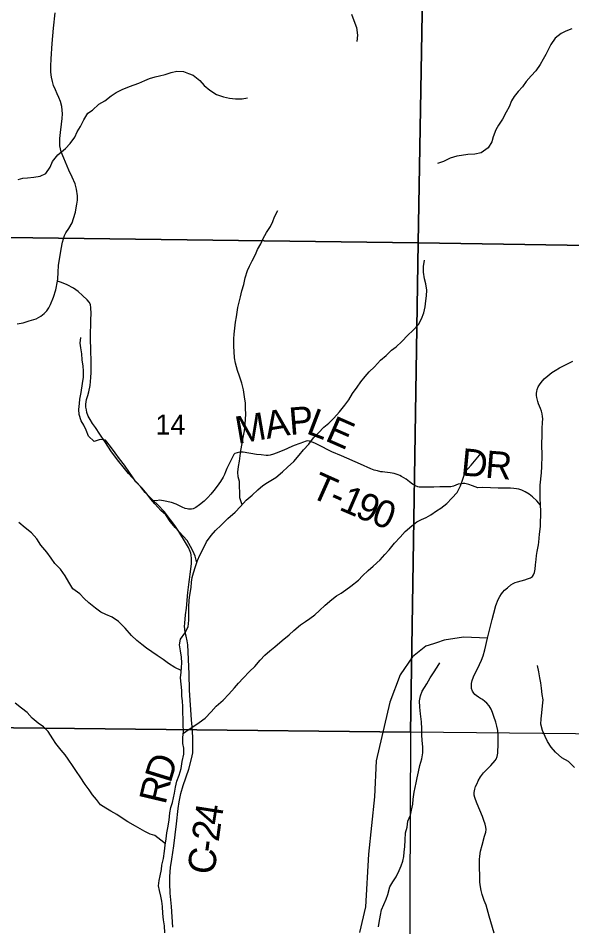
# Model space of a CAD drawing. Extents: x 0 to 34, y 0 to 22.
# Drawn here: x 24.164 to 25.315, y 15.161 to 17.051 of the extents above; entities that cross this region are included whole.
import ezdxf

# ---------------------------------------------------------------- set-up
doc = ezdxf.new("R2010")
doc.units = 0
for name, color, linetype in [('GM_X_Corporation', 7, 'Continuous'), ('GM_X_County_Road', 7, 'Continuous'), ('GM_X_County_Road_Text', 7, 'Continuous'), ('GM_X_Minor_River', 7, 'Continuous'), ('GM_X_Section_Text', 7, 'Continuous'), ('GM_X_State_Route', 7, 'Continuous'), ('GM_X_Township_Road', 7, 'Continuous'), ('GM_X_Township_Road_Text', 7, 'Continuous')]:
    doc.layers.add(name, color=color, linetype=linetype)

msp = doc.modelspace()

# ---------------------------------------------------------------- linework, layer by layer
at = {"layer": 'GM_X_Corporation'}
for points in [[(25.0136, 17.617), (24.9957, 16.5834), (23.9803, 16.5962), (23.994, 17.626)], [(26.0272, 17.5944), (26.0142, 16.5672), (24.9957, 16.5834), (25.0136, 17.617)], [(23.9803, 16.5962), (24.9957, 16.5834), (24.9795, 15.5656), (23.9634, 15.5762)], [(24.9957, 16.5834), (26.0142, 16.5672), (26.0085, 15.5549), (24.9795, 15.5656)], [(23.9634, 15.5762), (24.9795, 15.5656), (24.9754, 14.552), (23.9615, 14.5614), (23.9614, 14.5662)]]:
    msp.add_lwpolyline(points, close=True, dxfattribs=at)
at = {"layer": 'GM_X_County_Road'}
msp.add_lwpolyline([(24.4858, 15.1598), (24.4828, 15.2031), (24.4802, 15.2302), (24.4792, 15.2509), (24.4792, 15.2655), (24.481, 15.2837), (24.4834, 15.3015), (24.4879, 15.3293), (24.4933, 15.3746), (24.4964, 15.4066), (24.4984, 15.4204), (24.5022, 15.4376), (24.5073, 15.4548), (24.5188, 15.4884), (24.5245, 15.5097), (24.5269, 15.5223), (24.5274, 15.538), (24.5271, 15.5551), (24.5259, 15.5763), (24.5241, 15.5911), (24.5203, 15.6531), (24.5195, 15.6867), (24.5166, 15.7472), (24.5154, 15.7557), (24.5132, 15.7649), (24.5113, 15.7727), (24.5103, 15.7802), (24.5101, 15.7853), (24.5103, 15.7921), (24.5121, 15.8093), (24.5138, 15.8237), (24.5169, 15.8557), (24.5196, 15.878), (24.5202, 15.8827), (24.5218, 15.8939), (24.524, 15.9159), (24.5245, 15.9259), (24.5238, 15.934), (24.5228, 15.938), (24.5217, 15.9412), (24.5178, 15.9498), (24.512, 15.9601), (24.4979, 15.9829), (24.4898, 15.9952), (24.4807, 16.0072), (24.4674, 16.0244), (24.4541, 16.0381), (24.4445, 16.0471), (24.437, 16.0547), (24.4283, 16.0643), (24.418, 16.0766), (24.3936, 16.1034), (24.3822, 16.1171), (24.3734, 16.1284), (24.3645, 16.1402), (24.3568, 16.1507), (24.3454, 16.168), (24.3339, 16.1855), (24.3246, 16.1991), (24.3184, 16.2078), (24.3138, 16.2155), (24.3098, 16.2231), (24.307, 16.2302), (24.3059, 16.2359), (24.305, 16.2413), (24.3047, 16.2479), (24.3063, 16.2572), (24.3085, 16.266), (24.3108, 16.2735), (24.3134, 16.2866), (24.3153, 16.3033), (24.3157, 16.3139), (24.3157, 16.3235), (24.3156, 16.3382), (24.3151, 16.3585), (24.3144, 16.3858), (24.3154, 16.4234), (24.3159, 16.4366), (24.3154, 16.4482), (24.3141, 16.4548), (24.3116, 16.4598), (24.3075, 16.4648), (24.298, 16.474), (24.2888, 16.4818), (24.2787, 16.489), (24.2657, 16.4958), (24.2541, 16.5009), (24.2457, 16.5036)], dxfattribs=at)
at = {"layer": 'GM_X_Minor_River'}
for points in [[(24.8569, 17.0592), (24.8619, 17.0456), (24.8672, 17.0315), (24.8692, 17.0152), (24.8677, 17.0019)], [(25.315, 17.0288), (25.3025, 17.0238), (25.2926, 17.0188), (25.2801, 17.0089), (25.2711, 16.9956), (25.2658, 16.9846), (25.2609, 16.9751), (25.2552, 16.9652), (25.2491, 16.9545), (25.2401, 16.9409), (25.2302, 16.9306), (25.22, 16.9188), (25.212, 16.9081), (25.203, 16.8982), (25.195, 16.8879), (25.1893, 16.8784), (25.1844, 16.8663), (25.1784, 16.8549), (25.1705, 16.8404), (25.1621, 16.8282), (25.1572, 16.8187), (25.1516, 16.8039), (25.1489, 16.7937), (25.141, 16.7807), (25.1262, 16.7704), (25.1129, 16.7681), (25.0989, 16.7673), (25.0856, 16.765), (25.0758, 16.7634), (25.0617, 16.7592), (25.0481, 16.7527), (25.0356, 16.7481)], [(24.3799, 16.9024), (24.3955, 16.9086), (24.4049, 16.912), (24.4148, 16.9154), (24.4273, 16.9208), (24.4372, 16.925), (24.4485, 16.9288), (24.458, 16.9308), (24.4694, 16.9338), (24.4819, 16.9377), (24.4937, 16.9404), (24.5077, 16.9397), (24.518, 16.9355), (24.5278, 16.9321), (24.5415, 16.9212), (24.5503, 16.9106), (24.5624, 16.9011), (24.5765, 16.892), (24.5909, 16.8872), (24.6031, 16.8845), (24.616, 16.8831), (24.6296, 16.8831), (24.641, 16.885)], [(24.1637, 16.7154), (24.1735, 16.7177), (24.1834, 16.7185), (24.1967, 16.72), (24.2096, 16.722), (24.2217, 16.7273), (24.2308, 16.7406), (24.2353, 16.7524), (24.2463, 16.7661), (24.2622, 16.7794), (24.2724, 16.7897), (24.2815, 16.803), (24.2868, 16.8141), (24.2936, 16.8251), (24.3007, 16.8392), (24.3087, 16.8529), (24.3185, 16.8593), (24.3318, 16.8719), (24.3443, 16.8788), (24.3575, 16.8891), (24.3674, 16.8959), (24.3799, 16.9024)], [(24.6294, 16.0386), (24.625, 16.0526), (24.6246, 16.0651), (24.6242, 16.0749), (24.6238, 16.0867), (24.6215, 16.0966), (24.6207, 16.1061), (24.6222, 16.1182), (24.6241, 16.1289), (24.6256, 16.1406), (24.6271, 16.1513), (24.6297, 16.1661), (24.6316, 16.1782), (24.6346, 16.1923), (24.6361, 16.2063), (24.6368, 16.2166), (24.6372, 16.2272), (24.6367, 16.2386), (24.6363, 16.2496), (24.6348, 16.2633), (24.6321, 16.2777), (24.6287, 16.2917), (24.6241, 16.3057), (24.6199, 16.3175), (24.6161, 16.3327), (24.6137, 16.3444), (24.613, 16.3573), (24.6126, 16.3676), (24.6125, 16.3835), (24.6129, 16.393), (24.6144, 16.4055), (24.6159, 16.4184), (24.6177, 16.4291), (24.6207, 16.4488), (24.6237, 16.4598), (24.6264, 16.4712), (24.629, 16.4838), (24.6328, 16.4967), (24.6358, 16.5104), (24.6407, 16.5256), (24.6448, 16.5351), (24.6501, 16.5461), (24.6573, 16.559), (24.6618, 16.5693), (24.6682, 16.5815), (24.6732, 16.5925), (24.68, 16.6047), (24.6883, 16.6176), (24.6932, 16.6275), (24.697, 16.6377), (24.7038, 16.6507)], [(24.8204, 16.2187), (24.8318, 16.232), (24.8428, 16.2457), (24.8515, 16.2564), (24.859, 16.2697), (24.8689, 16.283), (24.8764, 16.2944), (24.8855, 16.3054), (24.8935, 16.3149), (24.9048, 16.3256), (24.9173, 16.3393), (24.9291, 16.3492), (24.94, 16.3599), (24.9499, 16.3668), (24.9616, 16.3778), (24.9738, 16.3911), (24.9844, 16.401), (24.9961, 16.4136), (25.0025, 16.4254), (25.007, 16.4375), (25.0097, 16.4501), (25.0112, 16.463), (25.0127, 16.4729), (25.0138, 16.4846), (25.0111, 16.4983), (25.0084, 16.5085), (25.0065, 16.5222), (25.0068, 16.534), (25.0087, 16.5472)], [(24.5351, 15.9175), (24.5316, 15.9316), (24.5277, 15.9414), (24.5224, 15.952), (24.5152, 15.9641), (24.4901, 15.9914), (24.4802, 16.0035), (24.4707, 16.0175), (24.4604, 16.0266), (24.4478, 16.0406), (24.4398, 16.0504), (24.4319, 16.0607), (24.4216, 16.0732), (24.4087, 16.0864), (24.4018, 16.0963), (24.3953, 16.1057), (24.385, 16.1209), (24.3748, 16.1337), (24.3656, 16.1466), (24.3557, 16.1599), (24.3455, 16.1727), (24.3345, 16.1742), (24.3223, 16.1704), (24.3105, 16.181), (24.3052, 16.1935), (24.3006, 16.2037), (24.2949, 16.2132), (24.2911, 16.2261), (24.2899, 16.2363), (24.2914, 16.2489), (24.2925, 16.2584), (24.2948, 16.2717), (24.2978, 16.2906), (24.2996, 16.3039), (24.3, 16.3172), (24.2992, 16.3271), (24.2973, 16.34), (24.2961, 16.3521), (24.2946, 16.365), (24.293, 16.3745), (24.2945, 16.3863)], [(24.4692, 15.1483), (24.468, 15.1623), (24.4664, 15.1748), (24.4649, 15.1885), (24.4637, 15.2025), (24.4626, 15.2139), (24.4603, 15.2242), (24.4576, 15.2363), (24.4557, 15.2458), (24.4568, 15.2568), (24.4594, 15.2663), (24.462, 15.2796), (24.4628, 15.2891), (24.4658, 15.3027), (24.468, 15.3179), (24.4699, 15.3301), (24.4718, 15.3434), (24.4732, 15.3563), (24.4751, 15.3662), (24.4777, 15.3821), (24.4792, 15.3973), (24.4815, 15.4087), (24.4845, 15.4193), (24.489, 15.4383), (24.4913, 15.4509), (24.4939, 15.4634), (24.4988, 15.4763), (24.5025, 15.4896), (24.5052, 15.5044), (24.5086, 15.5196), (24.5085, 15.5322), (24.5066, 15.5416), (24.5066, 15.5542), (24.5077, 15.5671), (24.5069, 15.5804), (24.5069, 15.5925), (24.5065, 15.6062), (24.5061, 15.6179), (24.5053, 15.6308), (24.5045, 15.6403), (24.5045, 15.6521), (24.5014, 15.6787), (24.5029, 15.6904), (24.5036, 15.6999), (24.5043, 15.7094), (24.5036, 15.7216), (24.5013, 15.7348), (24.4997, 15.747), (24.5016, 15.7587), (24.5103, 15.7717), (24.5171, 15.7846), (24.5189, 15.7983), (24.5189, 15.8256), (24.5196, 15.8397), (24.5211, 15.8507), (24.5234, 15.8662), (24.5245, 15.8776), (24.526, 15.8871), (24.5282, 15.897), (24.5327, 15.9103), (24.5369, 15.9228), (24.5414, 15.9335), (24.5486, 15.9468), (24.5558, 15.9616), (24.5652, 15.9746), (24.5739, 15.9848), (24.5861, 15.9959), (24.5997, 16.0096), (24.6152, 16.0233), (24.6262, 16.0351), (24.6379, 16.048), (24.6504, 16.0583), (24.6625, 16.0694), (24.6728, 16.0785), (24.6826, 16.085), (24.6993, 16.0949), (24.7137, 16.1071), (24.7239, 16.117), (24.7372, 16.1288), (24.7481, 16.1414), (24.7568, 16.1524), (24.7682, 16.1642), (24.778, 16.1776), (24.7883, 16.1878), (24.7992, 16.1996), (24.8095, 16.2084), (24.8204, 16.2187)], [(24.5074, 15.5633), (24.5194, 15.572), (24.5289, 15.5778), (24.5403, 15.5854), (24.5528, 15.5946), (24.5649, 15.6075), (24.5759, 15.6197), (24.5903, 15.6319), (24.6016, 15.6444), (24.6137, 15.6574), (24.6221, 15.6673), (24.6319, 15.6779), (24.6452, 15.6913), (24.6558, 15.7023), (24.6671, 15.7152), (24.677, 15.7255), (24.6872, 15.7347), (24.6974, 15.7427), (24.7129, 15.756), (24.727, 15.7682), (24.7368, 15.7766), (24.7512, 15.7884), (24.761, 15.7953), (24.7705, 15.8021), (24.7804, 15.8097), (24.7902, 15.8185), (24.8023, 15.8299), (24.816, 15.8417), (24.8254, 15.849), (24.8357, 15.8547), (24.8451, 15.8616), (24.8554, 15.8688), (24.8713, 15.8814), (24.88, 15.8909), (24.8913, 15.9016), (24.9016, 15.9107), (24.9163, 15.9241), (24.9262, 15.9347), (24.9349, 15.945), (24.9466, 15.9587), (24.958, 15.9709), (24.9682, 15.9827), (24.9822, 15.9949), (24.9924, 16.0029), (25.0023, 16.0075), (25.0118, 16.012), (25.0216, 16.0174), (25.0334, 16.0258), (25.0428, 16.0315), (25.0553, 16.041), (25.0656, 16.0525), (25.0762, 16.0643), (25.0833, 16.0779), (25.0886, 16.0916), (25.0931, 16.1072), (25.1053, 16.1205), (25.1162, 16.1331), (25.1264, 16.1456)], [(24.5031, 15.6935), (24.4896, 15.6999), (24.4766, 15.7086), (24.4652, 15.7165), (24.4527, 15.7248), (24.4421, 15.7327), (24.4307, 15.7399), (24.4208, 15.7479), (24.4105, 15.7558), (24.3999, 15.7668), (24.3866, 15.7819), (24.3725, 15.7955), (24.3592, 15.805), (24.3459, 15.8099), (24.336, 15.8148), (24.3246, 15.8231), (24.3109, 15.8348), (24.301, 15.8435), (24.2919, 15.8533), (24.2775, 15.8635), (24.2691, 15.8772), (24.2615, 15.8908), (24.2523, 15.9048), (24.2405, 15.9162), (24.2326, 15.9272), (24.2234, 15.94), (24.2109, 15.9544), (24.2025, 15.9673), (24.1915, 15.9802), (24.1789, 15.9908), (24.1652, 16.0017)], [(24.9131, 15.1603), (24.9146, 15.1698), (24.9172, 15.1846), (24.9195, 15.1956), (24.924, 15.207), (24.9289, 15.2181), (24.9327, 15.2276), (24.9364, 15.2435), (24.9425, 15.2542), (24.95, 15.2644), (24.9561, 15.2774), (24.9599, 15.2876), (24.9636, 15.2971), (24.9655, 15.3066), (24.9666, 15.3161), (24.9674, 15.3279), (24.9685, 15.3408), (24.9692, 15.356), (24.9726, 15.3678), (24.9741, 15.3803), (24.9794, 15.3925), (24.9816, 15.4035), (24.9842, 15.416), (24.9854, 15.4263), (24.9872, 15.4403), (24.9891, 15.4502), (24.9914, 15.4601), (24.9932, 15.4703), (24.9959, 15.4832), (24.9992, 15.4958), (25.003, 15.5098), (25.0049, 15.5227), (25.0052, 15.5349), (25.0041, 15.5478), (25.0029, 15.5599), (25.0032, 15.5721), (25.0025, 15.5869), (25.0005, 15.6036), (24.999, 15.6172), (24.9982, 15.6309), (25.0001, 15.6412), (25.0035, 15.6507), (25.0133, 15.6659), (25.0205, 15.6784), (25.0273, 15.6887), (25.0352, 15.7005), (25.0405, 15.71)], [(25.3206, 15.4919), (25.3081, 15.5047), (25.2944, 15.5123), (25.2811, 15.524), (25.272, 15.5342), (25.264, 15.5463), (25.2594, 15.5566), (25.2537, 15.5691), (25.2506, 15.5824), (25.2514, 15.593), (25.2525, 15.6059), (25.254, 15.6199), (25.2551, 15.6329), (25.2532, 15.6435), (25.2516, 15.6568), (25.2501, 15.6681), (25.2485, 15.6784), (25.2462, 15.6909), (25.2435, 15.7042)], [(24.4703, 15.3329), (24.4604, 15.3411), (24.4482, 15.3505), (24.4383, 15.3535), (24.4273, 15.3588), (24.4178, 15.3645), (24.4076, 15.3701), (24.392, 15.3792), (24.3802, 15.3864), (24.3688, 15.3939), (24.3563, 15.4011), (24.346, 15.4071), (24.3354, 15.4143), (24.3266, 15.4253), (24.3186, 15.4351), (24.3118, 15.4454), (24.303, 15.4567), (24.2927, 15.4726), (24.2855, 15.4836), (24.2783, 15.4938), (24.268, 15.509), (24.2619, 15.5185), (24.2532, 15.5283), (24.2425, 15.5419), (24.2364, 15.5518), (24.2265, 15.5669), (24.217, 15.5764), (24.2056, 15.5839), (24.1934, 15.5949), (24.1824, 15.6066), (24.171, 15.6157), (24.1581, 15.6255)]]:
    msp.add_lwpolyline(points, dxfattribs=at)
at = {"layer": 'GM_X_State_Route'}
msp.add_lwpolyline([(24.1617, 16.4145), (24.1746, 16.4171), (24.1869, 16.4211), (24.2012, 16.4255), (24.2109, 16.4305), (24.2182, 16.4361), (24.2234, 16.4418), (24.2275, 16.4479), (24.2314, 16.4552), (24.2377, 16.4702), (24.2423, 16.4856), (24.2457, 16.5036), (24.2464, 16.5084), (24.2471, 16.5218), (24.248, 16.5372), (24.2512, 16.557), (24.2534, 16.5704), (24.2562, 16.5849), (24.2582, 16.5919), (24.2603, 16.5983), (24.2634, 16.6042), (24.2696, 16.6132), (24.2761, 16.6248), (24.2793, 16.6342), (24.283, 16.6471), (24.2848, 16.6559), (24.2863, 16.6635), (24.2871, 16.6721), (24.2873, 16.6814), (24.285, 16.695), (24.2823, 16.7061), (24.2761, 16.72), (24.2696, 16.7343), (24.2586, 16.7597), (24.2536, 16.7725), (24.2509, 16.7849), (24.2503, 16.7918), (24.2503, 16.8002), (24.2518, 16.8126), (24.2539, 16.8302), (24.2555, 16.8419), (24.2559, 16.852), (24.2557, 16.8592), (24.2546, 16.8671), (24.2521, 16.8774), (24.2487, 16.8858), (24.2453, 16.8933), (24.2416, 16.9017), (24.2377, 16.9105), (24.2352, 16.9187), (24.233, 16.9276), (24.2318, 16.9383), (24.2316, 16.951), (24.2326, 16.9664), (24.235, 16.9982), (24.2378, 17.0302), (24.2412, 17.0618)], dxfattribs=at)
at = {"layer": 'GM_X_Township_Road'}
for points in [[(25.1532, 15.147), (25.1433, 15.1827), (25.1366, 15.2053), (25.1328, 15.215), (25.1286, 15.2275), (25.1262, 15.2362), (25.1248, 15.244), (25.1239, 15.2533), (25.1236, 15.263), (25.1229, 15.2874), (25.1229, 15.3003), (25.1239, 15.3078), (25.1253, 15.3181), (25.1282, 15.3303), (25.1332, 15.349), (25.1359, 15.3577), (25.1367, 15.3628), (25.1363, 15.3677), (25.1345, 15.3744), (25.1322, 15.3818), (25.1293, 15.39), (25.118, 15.4162), (25.1145, 15.4256), (25.1131, 15.4297), (25.1119, 15.4344), (25.1121, 15.4402), (25.1132, 15.4466), (25.1148, 15.4521), (25.1179, 15.4589), (25.1203, 15.4644), (25.1251, 15.4722), (25.1315, 15.4808), (25.1379, 15.4879), (25.1465, 15.4959), (25.1554, 15.5062), (25.1577, 15.5093), (25.1597, 15.5146), (25.1608, 15.522), (25.1614, 15.5416), (25.1615, 15.56), (25.1611, 15.569), (25.1593, 15.5776), (25.1567, 15.5864), (25.1528, 15.5977), (25.1501, 15.6061), (25.1472, 15.6135), (25.1428, 15.6201), (25.1384, 15.6255), (25.1343, 15.6295), (25.1295, 15.6331), (25.1253, 15.6355), (25.1212, 15.6384), (25.116, 15.6417), (25.1131, 15.6439), (25.1113, 15.6465), (25.1081, 15.6506), (25.1066, 15.6561), (25.106, 15.6609), (25.1062, 15.6665), (25.1077, 15.673), (25.1105, 15.6808), (25.123, 15.7062), (25.1268, 15.7149), (25.1304, 15.7243), (25.1342, 15.7368), (25.1398, 15.7612), (25.149, 15.8001), (25.1524, 15.8133), (25.1567, 15.8288), (25.1619, 15.8413), (25.1652, 15.8476), (25.1685, 15.853), (25.1712, 15.8564), (25.1752, 15.8605), (25.1812, 15.8658), (25.1881, 15.8717), (25.1927, 15.8749), (25.1971, 15.8768), (25.202, 15.8785), (25.2169, 15.8826), (25.2226, 15.8845), (25.2291, 15.8867), (25.2328, 15.8892), (25.2353, 15.8924), (25.2375, 15.8978), (25.2386, 15.9046), (25.2391, 15.9136), (25.2405, 15.9249), (25.2415, 15.933), (25.2429, 15.9414), (25.2453, 15.9549), (25.2462, 15.9605), (25.2476, 15.9774), (25.2494, 15.9934), (25.2505, 16.026), (25.2498, 16.0379), (25.249, 16.0528), (25.2487, 16.0637), (25.2493, 16.0792), (25.252, 16.105), (25.2528, 16.1182), (25.2532, 16.1404), (25.2527, 16.1645), (25.253, 16.1834), (25.2534, 16.197), (25.2539, 16.2094), (25.2544, 16.2171), (25.2541, 16.222), (25.2535, 16.2273), (25.2516, 16.2333), (25.2497, 16.2387), (25.2457, 16.2485), (25.2441, 16.2534), (25.2418, 16.2614), (25.2413, 16.2659), (25.2414, 16.2706), (25.2419, 16.2741), (25.2427, 16.2784), (25.2449, 16.2837), (25.2474, 16.2878), (25.2508, 16.2928), (25.2576, 16.3004), (25.2651, 16.307), (25.273, 16.3133), (25.28, 16.3181), (25.2894, 16.3236), (25.2991, 16.3285), (25.3088, 16.333), (25.317, 16.3374)], [(25.2498, 16.0379), (25.2423, 16.0467), (25.2334, 16.0547), (25.2259, 16.0605), (25.2182, 16.0653), (25.211, 16.0686), (25.2048, 16.0706), (25.1996, 16.0717), (25.1946, 16.0724), (25.1876, 16.0729), (25.175, 16.0728), (25.162, 16.073), (25.1297, 16.0742), (25.1192, 16.0739), (25.1082, 16.0779), (25.1005, 16.0809), (25.0924, 16.0824), (25.0881, 16.0827), (25.0843, 16.0823), (25.0786, 16.081), (25.0736, 16.0789), (25.069, 16.0772), (25.0634, 16.0761), (25.0583, 16.0758), (25.0494, 16.0755), (25.0402, 16.0756), (25.0277, 16.0749), (25.0184, 16.0748), (25.0096, 16.0748), (25.0007, 16.0749), (24.9973, 16.0754), (24.9945, 16.0761), (24.9886, 16.0786), (24.9839, 16.0811), (24.9773, 16.0865), (24.9706, 16.0914), (24.9658, 16.0945), (24.9611, 16.0971), (24.9575, 16.099), (24.9541, 16.1005), (24.9456, 16.1034), (24.937, 16.1051), (24.9259, 16.1063), (24.9214, 16.1068), (24.9179, 16.1073), (24.9106, 16.1089), (24.9042, 16.1103), (24.8973, 16.1129), (24.8754, 16.1227), (24.836, 16.1402), (24.8162, 16.1489), (24.7875, 16.1631), (24.7804, 16.1666), (24.7751, 16.1689), (24.7696, 16.1705), (24.765, 16.1712), (24.7608, 16.1701), (24.757, 16.1685), (24.7498, 16.1659), (24.7379, 16.1615), (24.7332, 16.1595), (24.7161, 16.1523), (24.7001, 16.1455), (24.6949, 16.1436), (24.688, 16.1418), (24.6834, 16.1411), (24.6796, 16.141), (24.6688, 16.1421), (24.6594, 16.1432), (24.6314, 16.1479), (24.6246, 16.1479), (24.6189, 16.1468), (24.6146, 16.145), (24.6123, 16.1431), (24.605, 16.1278), (24.6007, 16.1197), (24.5978, 16.1137), (24.5952, 16.1072), (24.5928, 16.1017), (24.59, 16.096), (24.5846, 16.0868), (24.5777, 16.0772), (24.5708, 16.0681), (24.5647, 16.0604), (24.5583, 16.0534), (24.5509, 16.046), (24.5412, 16.038), (24.5334, 16.0329), (24.528, 16.0301), (24.5246, 16.0294), (24.5219, 16.029), (24.5184, 16.0292), (24.515, 16.0298), (24.5111, 16.031), (24.5051, 16.0335), (24.4924, 16.0394), (24.4828, 16.0429), (24.4664, 16.0466), (24.4581, 16.0477), (24.4513, 16.0468), (24.4445, 16.0471)], [(25.0333, 15.7513), (25.0273, 15.7493), (25.0116, 15.7441), (24.9834, 15.7221), (24.9583, 15.6845), (24.9364, 15.6281), (24.9082, 15.5059), (24.905, 15.4307), (24.8925, 15.3116), (24.8862, 15.2019), (24.8736, 15.1489)], [(25.1398, 15.7612), (25.09, 15.7628), (25.0492, 15.7566), (25.0333, 15.7513)]]:
    msp.add_lwpolyline(points, dxfattribs=at)

# ---------------------------------------------------------------- texts
at = {"layer": 'GM_X_County_Road_Text'}
for s, rotation, p in [('D', 72.9222, (24.4806, 15.4577)), ('R', 76.6321, (24.47, 15.4132)), ('4', 81.0814, (24.5852, 15.3702)), ('2', 82.3382, (24.5807, 15.3361)), ('-', 82.3931, (24.5776, 15.3132)), ('C', 82.4072, (24.5715, 15.2673))]:
    msp.add_text(s, height=0.0568, rotation=rotation, dxfattribs=at).set_placement(p)
at = {"layer": 'GM_X_Section_Text'}
msp.add_text('14', height=0.04186, rotation=0, dxfattribs=at).set_placement((24.4494, 16.1843))
at = {"layer": 'GM_X_Township_Road_Text'}
for s, rotation, p in [('A', 9.7073, (24.6811, 16.1753)), ('P', 4.7522, (24.7291, 16.1836)), ('L', 339.0422, (24.7607, 16.1877)), ('M', 9.7678, (24.6204, 16.1649)), ('E', 336.3878, (24.7997, 16.1728)), ('D', 354.575, (25.0828, 16.0998)), ('R', 355.4077, (25.1335, 16.0949)), ('T', 335.9657, (24.768, 16.056)), ('1', 336.6202, (24.8288, 16.0289)), ('-', 336.1185, (24.807, 16.0386)), ('9', 337.4374, (24.8617, 16.0147)), ('0', 338.6826, (24.8953, 16.0008))]:
    msp.add_text(s, height=0.0568, rotation=rotation, dxfattribs=at).set_placement(p)

doc.saveas('drawing.dxf')
